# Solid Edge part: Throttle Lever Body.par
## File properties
Author: m_hel
Template: iso metric part.par
Last saved by: m_hel
Revision: 4
Application: Solid Edge
Accuracy: 0,990
Username: m_hel
Material: Rubber
Face Style: Black (dull)
Fill Style: Normal
Virtual Style: Normal
Grouping: Uncategorized
LibraryName: Custom Materials
Coef. of Thermal Exp: 0.0
Thermal Conductivity: 0.0
Specific Heat: 0.0
Modulus of Elasticity: 0.0
Poisson's Ratio: 0.0
Yield Stress: 0.0
Ultimate Stress: 0.0
Elongation: 0.0
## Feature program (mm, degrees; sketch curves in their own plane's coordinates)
make body feature "unnamed MakeBodyFeature 1"
sketch for "ExtrudedProtrusion_3" plane through (0, 0, 0) normal (0, 0, 1) x-axis (1, 0, 0)
  line (-40, -75) -> (40, -75)
  line (40, -75) -> (40, 75)
  line (40, 75) -> (-40, 75)
  line (-40, 75) -> (-40, -75)
extrude "ExtrudedProtrusion_3" add finite 20 along -normal
sketch for "unnamed Cutout 1" plane through (-50, 0, 29.0577) normal (-1, 0, 0) x-axis (0, -1, 0)
  circle centre (0, 0.9423) radius 15
extrude "unnamed Cutout 1" cut finite 50 along -normal
fillet "Round_2" radius 5
Other named dimensions: "SweptSurface_4": Scale_Start = 1; Scale_End = 1 | "ExtrudedSurface_3": FiniteDepth = 110.6024 mm
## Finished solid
Body 1: solid body, 19 faces, 40 edges, 24 vertices.
  Faces by surface: plane 9, blend 4, torus 3, spline 2, cylinder 1
  Edges by curve: intersection 14, line 14, circle 12
Body 2: solid body, 6 faces, 12 edges, 8 vertices.
  Faces by surface: plane 3, spline 2, torus 1
  Edges by curve: circle 4, curve on surface 2, intersection 2, line 2, spline 2
Body 3: sheet body, 1 face, 4 edges, 4 vertices.
  Faces by surface: plane 1
  Edges by curve: line 4
Bounding box of the edges (mm; curved faces can reach further): 110.602 x 211.262 x 82.865, from (-55.3012, -101.796, -20) to (55.3012, 109.4664, 62.8653).
Cylindrical faces by radius (mm): R15 x1
Toroidal faces (ring radius, tube radius in mm): R144.6943 r111.1618 x2, R240.847 r5 x2
Planar faces by outward normal: +x 3, +y 1, -x 4, -y 1, -z 3
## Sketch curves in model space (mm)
arc centre (0, 0, -41.1618) radius 111.1618 from (50, 0, 58.1204) through (0, 0, 70) to (-50, 0, 58.1204)
spline (0, 60, 62.8653) -> (0, 86.1515, 38.7888) -> (0, 95, 0)
arc centre (0, 0, -185.8562) radius 255.8562 from (0, 0, 70) through (0, 30.2114, 68.2101) to (0, 60, 62.8653)
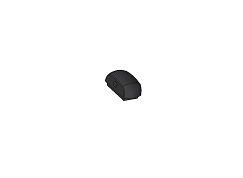
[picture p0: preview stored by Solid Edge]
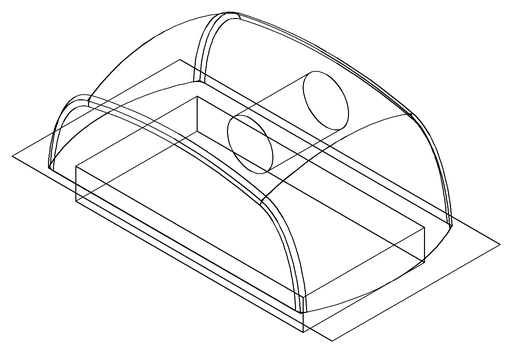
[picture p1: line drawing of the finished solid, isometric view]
